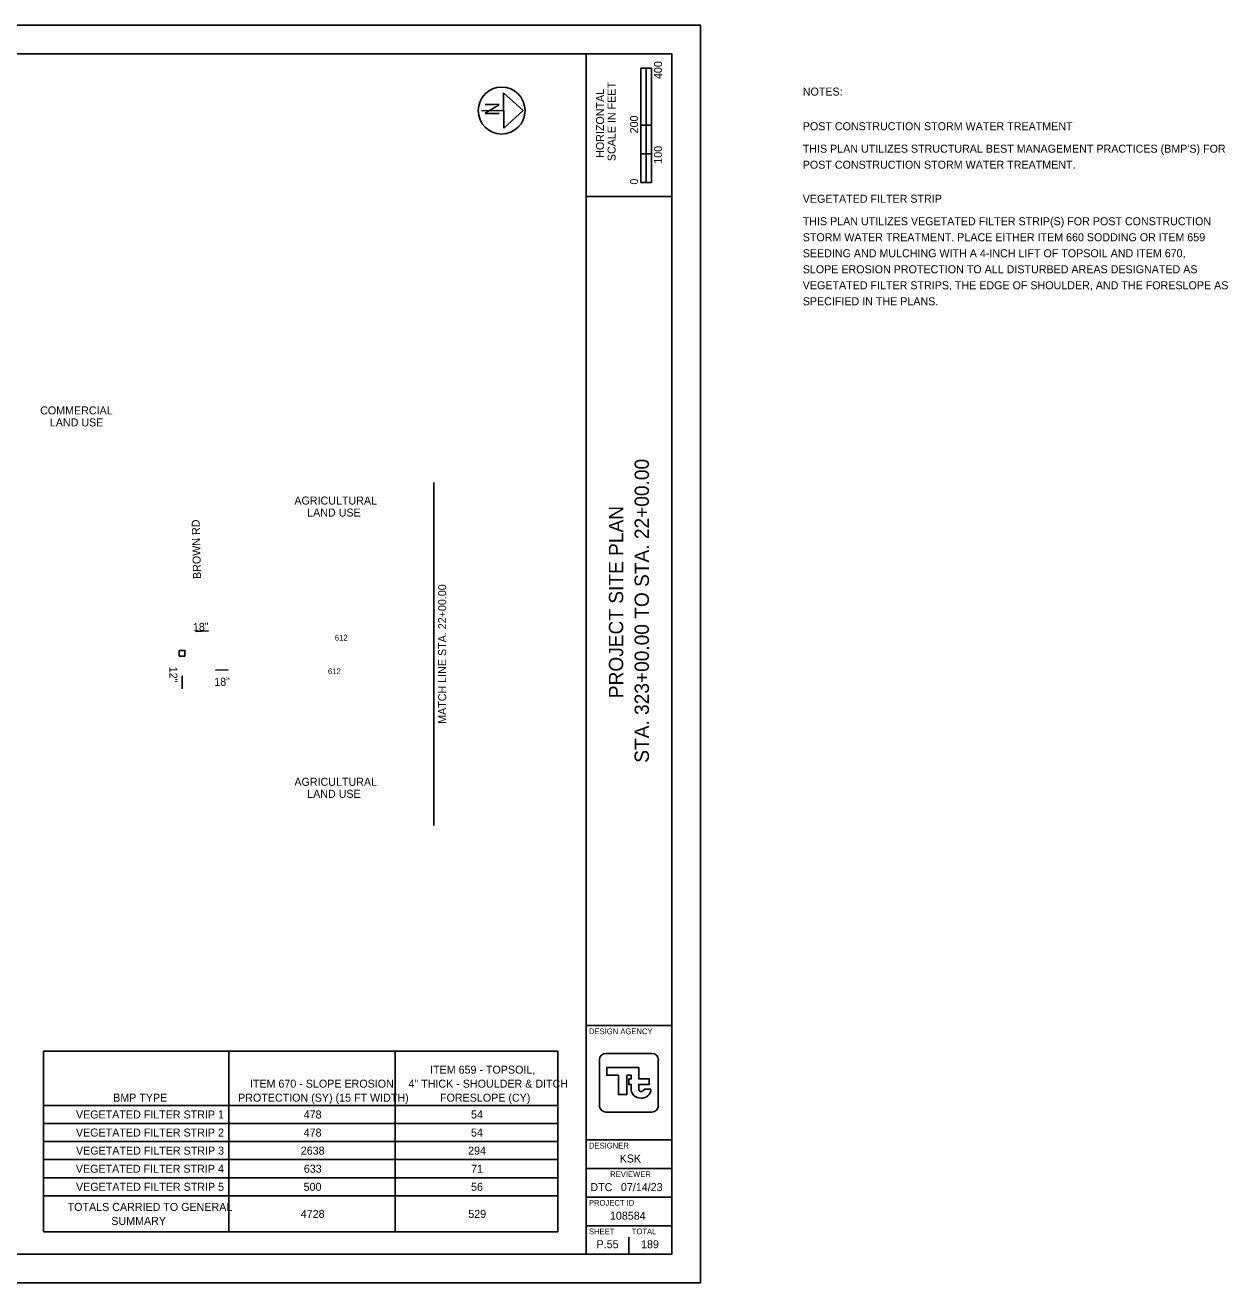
# Model space of a CAD drawing. Extents: x -0.5 to 43.2, y 0 to 22.
# Drawn here: x 22.18 to 43.23, y 0 to 22 of the extents above; entities that cross this region are included whole.
import ezdxf

# ---------------------------------------------------------------- set-up
doc = ezdxf.new("R2010")
doc.units = 0
for name, color, linetype in [('BR_X_Beam_Centerline', 7, 'Continuous'), ('DR_X_Cells', 7, 'Continuous'), ('GK_Drainage_Nodes', 7, 'Continuous'), ('MD_P_Surface_Asphalt_Concrete_Surface_Course', 7, 'Continuous'), ('PV_P_EOP', 7, 'Continuous'), ('SC_Scratch6', 7, 'Continuous')]:
    doc.layers.add(name, color=color, linetype=linetype)

msp = doc.modelspace()

# ---------------------------------------------------------------- linework, layer by layer
at = {"layer": 'BR_X_Beam_Centerline'}
for p, q in [((32.957, 19.25), (32.957, 21.25)), ((33.144, 21.25), (32.957, 21.25)), ((32.957, 20.25), (32.957, 21.25)), ((32.957, 21.25), (33.05, 21.25)), ((33.05, 21.25), (33.051, 21.25)), ((33.051, 21.25), (33.051, 20.25)), ((33.144, 21.25), (33.144, 19.25)), ((33.051, 20.25), (32.957, 20.25)), ((33.143, 20.25), (33.05, 20.25)), ((33.05, 20.25), (33.05, 19.75)), ((33.143, 19.75), (33.143, 20.25)), ((33.05, 19.75), (32.957, 19.75)), ((32.957, 19.75), (32.957, 19.25)), ((33.05, 19.25), (33.05, 19.75)), ((33.05, 19.75), (33.143, 19.75)), ((33.144, 19.25), (32.957, 19.25)), ((32.957, 19.25), (33.05, 19.25)), ((29.336, 8.001), (29.336, 14.001)), ((22.508, 4.052), (25.749, 4.052)), ((22.508, 4.052), (22.508, 3.103)), ((25.749, 4.052), (28.661, 4.052)), ((25.749, 4.052), (25.749, 3.103)), ((28.661, 4.052), (31.508, 4.052)), ((28.661, 4.052), (28.661, 3.103)), ((31.508, 4.052), (31.508, 3.103)), ((32.75, 3.5), (32.75, 3.5)), ((32.791, 3.415), (32.791, 3.415)), ((33.136, 3.385), (33.015, 3.385)), ((22.508, 3.103), (25.749, 3.103)), ((22.508, 3.103), (22.508, 2.155)), ((25.749, 3.103), (28.661, 3.103)), ((25.749, 3.103), (25.749, 2.155)), ((28.661, 3.103), (31.508, 3.103)), ((28.661, 3.103), (28.661, 2.155)), ((31.508, 3.103), (31.508, 2.155)), ((22.508, 2.787), (25.749, 2.787)), ((25.749, 2.787), (28.661, 2.787)), ((28.661, 2.787), (31.508, 2.787)), ((22.508, 2.471), (25.749, 2.471)), ((25.749, 2.471), (28.661, 2.471)), ((28.661, 2.471), (31.508, 2.471)), ((22.508, 2.155), (25.749, 2.155)), ((22.508, 2.155), (22.508, 0.89)), ((25.749, 2.155), (28.661, 2.155)), ((25.749, 2.155), (25.749, 0.89)), ((28.661, 2.155), (31.508, 2.155)), ((28.661, 2.155), (28.661, 0.89)), ((31.508, 2.155), (31.508, 0.89)), ((22.508, 1.838), (25.749, 1.838)), ((25.749, 1.838), (28.661, 1.838)), ((28.661, 1.838), (31.508, 1.838)), ((22.508, 1.522), (25.749, 1.522)), ((25.749, 1.522), (28.661, 1.522)), ((28.661, 1.522), (31.508, 1.522)), ((22.508, 0.89), (25.749, 0.89)), ((25.749, 0.89), (28.661, 0.89)), ((28.661, 0.89), (31.508, 0.89)), ((32.375, 0.675), (32.375, 0.675)), ((32.75, 0.5), (32.75, 0.8))]:
    msp.add_line(p, q, dxfattribs=at)
for points in [[(32.348, 4.014), (33.152, 4.014)], [(32.236, 3.099), (32.236, 3.901)], [(32.922, 3.399), (32.922, 3.47), (33.107, 3.47), (33.107, 3.568), (32.922, 3.568), (32.922, 3.768), (32.361, 3.768), (32.361, 3.632), (32.566, 3.632), (32.566, 3.294), (32.715, 3.294), (32.715, 3.63), (32.79, 3.63), (32.79, 3.568), (32.748, 3.568), (32.748, 3.47), (32.79, 3.47), (32.79, 3.415), (32.791, 3.415)], [(33.264, 3.901), (33.264, 3.099)], [(33.152, 2.986), (32.348, 2.986)]]:
    msp.add_lwpolyline(points, dxfattribs=at)
for centre, radius, start, end in [((32.348, 3.901), 0.113, 90, 180), ((33.152, 3.901), 0.113, 360, 90), ((32.949, 3.392), 0.16, 171.8856, 274.8323), ((32.968, 3.392), 0.0473, 171.8856, 350.9243), ((32.976, 3.392), 0.16, 265.1677, 357.3201), ((32.348, 3.099), 0.113, 180, 270), ((33.152, 3.099), 0.113, 270, 360)]:
    msp.add_arc(centre, radius, start, end, dxfattribs=at)
at = {"layer": 'DR_X_Cells'}
msp.add_lwpolyline([(0, 0), (34, 0), (34, 22), (0, 22)], close=True, dxfattribs=at)
at = {"layer": 'GK_Drainage_Nodes'}
for p, q in [((32, 0.5), (32, 21.5)), ((32, 19), (33.5, 19)), ((32, 4.5), (33.5, 4.5)), ((32, 2.5), (33.5, 2.5)), ((32, 2), (33.5, 2)), ((32, 1.5), (33.5, 1.5)), ((32, 1), (33.5, 1))]:
    msp.add_line(p, q, dxfattribs=at)
msp.add_lwpolyline([(1.5, 21.5), (33.5, 21.5), (33.5, 0.5), (1.5, 0.5)], close=True, dxfattribs=at)
at = {"layer": 'MD_P_Surface_Asphalt_Concrete_Surface_Course'}
for p, q in [((25.393, 11.404), (25.167, 11.395)), ((24.934, 10.393), (24.933, 10.619)), ((25.74, 10.722), (25.514, 10.715))]:
    msp.add_line(p, q, dxfattribs=at)
at = {"layer": 'PV_P_EOP'}
for p, q in [((30.898, 20.509), (30.554, 20.814)), ((30.554, 20.814), (30.559, 20.198)), ((30.557, 20.506), (30.17, 20.503)), ((30.559, 20.198), (30.898, 20.509))]:
    msp.add_line(p, q, dxfattribs=at)
msp.add_lwpolyline([(24.882, 11.064), (24.982, 11.064), (24.982, 10.964), (24.882, 10.964)], close=True, dxfattribs=at)
msp.add_circle((30.524, 20.506), 0.41, dxfattribs=at)
at = {"layer": 'SC_Scratch6'}
msp.add_circle((30.524, 20.506), 0.41, dxfattribs=at)

# ---------------------------------------------------------------- texts
at = {"layer": 'BR_X_Beam_Centerline'}
for s, height, p in [('400', 0.14, (33.33, 21.057)), ('SCALE IN FEET', 0.14, (32.517, 19.621)), ('HORIZONTAL', 0.14, (32.315, 19.679)), ('200', 0.14, (32.91, 20.107)), ('100', 0.14, (33.33, 19.577)), ('0', 0.14, (32.91, 19.211)), ('STA. 323+00.00 TO STA. 22+00.00', 0.25, (33.1, 9.098)), ('PROJECT SITE PLAN', 0.25, (32.65, 10.227)), ('MATCH LINE STA. 22+00.00', 0.14, (29.552, 9.779))]:
    msp.add_text(s, height=height, rotation=90, dxfattribs=at).set_placement(p)
for s, height, p in [('DESIGN AGENCY', 0.1, (32.05, 4.35)), ('DESIGNER', 0.1, (32.05, 2.35)), ('KSK', 0.14, (32.588, 2.105)), ('REVIEWER', 0.1, (32.422, 1.85)), ('DTC', 0.14, (32.076, 1.605)), ('07/14/23', 0.14, (32.611, 1.605)), ('PROJECT ID', 0.1, (32.05, 1.35)), ('108584', 0.14, (32.418, 1.105)), ('SHEET', 0.1, (32.05, 0.85)), ('TOTAL', 0.1, (32.8, 0.85)), ('P.55', 0.14, (32.185, 0.605)), ('189', 0.14, (32.963, 0.605))]:
    msp.add_text(s, height=height, dxfattribs=at).set_placement(p)
at = {"layer": 'MD_P_Surface_Asphalt_Concrete_Surface_Course'}
for s, rotation, p in [('18"', 2.2016, (25.123, 11.399)), ('12"', 270.1695, (24.708, 10.777)), ('18"', 1.8191, (25.496, 10.439))]:
    msp.add_text(s, height=0.14, rotation=rotation, dxfattribs=at).set_placement(p)
at = {"layer": 'PV_P_EOP'}
for s, height, p in [('NOTES:', 0.14, (35.792, 20.768)), ('POST CONSTRUCTION STORM WATER TREATMENT', 0.14, (35.792, 20.162)), ("THIS PLAN UTILIZES STRUCTURAL BEST MANAGEMENT PRACTICES (BMP'S) FOR ", 0.14, (35.792, 19.769)), ('POST CONSTRUCTION STORM WATER TREATMENT.', 0.14, (35.792, 19.489)), ('VEGETATED FILTER STRIP', 0.14, (35.792, 18.893)), ('THIS PLAN UTILIZES VEGETATED FILTER STRIP(S) FOR POST CONSTRUCTION ', 0.14, (35.792, 18.5)), ('STORM WATER TREATMENT. PLACE EITHER ITEM 660 SODDING OR ITEM 659 ', 0.14, (35.792, 18.22)), ('SEEDING AND MULCHING WITH A 4-INCH LIFT OF TOPSOIL AND ITEM 670, ', 0.14, (35.792, 17.94)), ('SLOPE EROSION PROTECTION TO ALL DISTURBED AREAS DESIGNATED AS ', 0.14, (35.792, 17.66)), ('VEGETATED FILTER STRIPS, THE EDGE OF SHOULDER, AND THE FORESLOPE AS ', 0.14, (35.792, 17.38)), ('SPECIFIED IN THE PLANS.', 0.14, (35.792, 17.1)), ('COMMERCIAL', 0.14, (22.447, 15.191)), ('LAND USE', 0.14, (22.617, 14.981)), ('AGRICULTURAL ', 0.14, (26.896, 13.614)), ('LAND USE', 0.14, (27.12, 13.404)), ('612', 0.1, (27.604, 11.235)), ('612', 0.1, (27.484, 10.648)), ('AGRICULTURAL ', 0.14, (26.896, 8.694)), ('LAND USE', 0.14, (27.12, 8.484)), ('ITEM 659 - TOPSOIL,', 0.14, (29.271, 3.659)), ('ITEM 670 - SLOPE EROSION ', 0.14, (26.118, 3.414)), (' 4" THICK - SHOULDER & DITCH ', 0.14, (28.841, 3.414)), ('BMP TYPE', 0.14, (23.725, 3.169)), ('PROTECTION (SY) (15 FT WIDTH)', 0.14, (25.911, 3.169)), ('FORESLOPE (CY)', 0.14, (29.445, 3.169)), ('VEGETATED FILTER STRIP 1', 0.14, (23.074, 2.875)), ('478', 0.14, (27.059, 2.875)), ('54', 0.14, (29.987, 2.875)), ('VEGETATED FILTER STRIP 2', 0.14, (23.074, 2.559)), ('478', 0.14, (27.059, 2.559)), ('54', 0.14, (29.987, 2.559)), ('VEGETATED FILTER STRIP 3', 0.14, (23.075, 2.243)), ('2638', 0.14, (27.008, 2.243)), ('294', 0.14, (29.936, 2.243)), ('VEGETATED FILTER STRIP 4', 0.14, (23.072, 1.926)), ('633', 0.14, (27.061, 1.926)), ('71', 0.14, (29.989, 1.926)), ('VEGETATED FILTER STRIP 5', 0.14, (23.075, 1.61)), ('500', 0.14, (27.058, 1.61)), ('56', 0.14, (29.988, 1.61)), ('TOTALS CARRIED TO GENERAL ', 0.14, (22.928, 1.258)), ('SUMMARY', 0.14, (23.693, 1.013)), ('4728', 0.14, (27.008, 1.136)), ('529', 0.14, (29.939, 1.136))]:
    msp.add_text(s, height=height, dxfattribs=at).set_placement(p)
for s, height, rotation, p in [('N', 0.25, 270.4913, (30.232, 20.654)), ('BROWN RD', 0.14, 91.4423, (25.264, 12.314))]:
    msp.add_text(s, height=height, rotation=rotation, dxfattribs=at).set_placement(p)

doc.saveas('drawing.dxf')
